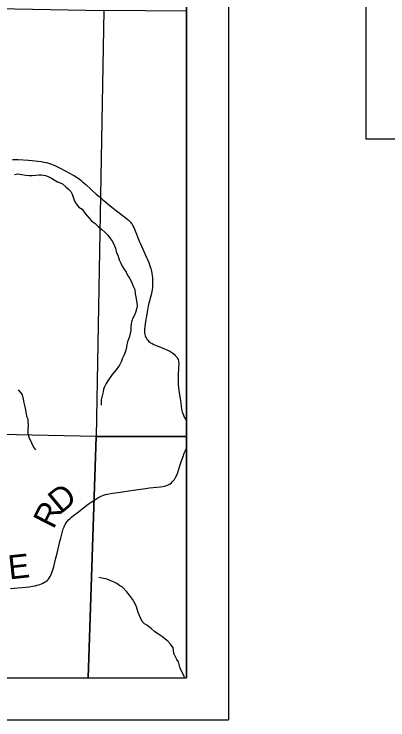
# Model space of a CAD drawing. Extents: x -7.1 to 34, y 0 to 22.
# Drawn here: x 8.492 to 9.377, y 14 to 15.673 of the extents above; entities that cross this region are included whole.
import ezdxf

# ---------------------------------------------------------------- set-up
doc = ezdxf.new("R2010")
doc.units = 0
for name, color, linetype in [('GM_X_County_Road', 7, 'Continuous'), ('GM_X_County_Road_Text', 7, 'Continuous'), ('GM_X_Minor_River', 7, 'Continuous'), ('GM_X_Section', 7, 'Continuous'), ('GM_X_Township_Road', 7, 'Continuous'), ('GM_X_Unincorporated', 7, 'Continuous'), ('SH_Cut_Line', 7, 'Continuous'), ('SH_Data', 7, 'Continuous'), ('SH_Text', 7, 'Continuous')]:
    doc.layers.add(name, color=color, linetype=linetype)

msp = doc.modelspace()

# ---------------------------------------------------------------- linework, layer by layer
at = {"layer": 'GM_X_County_Road'}
for points in [[(8.4874, 15.3285), (8.5008, 15.3278), (8.5254, 15.3267), (8.5342, 15.3258), (8.5479, 15.3241), (8.5556, 15.3231), (8.5623, 15.322), (8.5681, 15.3207), (8.5734, 15.3191), (8.5799, 15.317), (8.5844, 15.3154), (8.5929, 15.3119), (8.601, 15.3079), (8.6247, 15.2951), (8.6303, 15.292), (8.6348, 15.2891), (8.6406, 15.2855), (8.6463, 15.2815), (8.6503, 15.2786), (8.6539, 15.2755), (8.6614, 15.2686), (8.6731, 15.2579), (8.6774, 15.2539), (8.6863, 15.2461), (8.6933, 15.2401), (8.7008, 15.2337), (8.7088, 15.2271), (8.7193, 15.2183), (8.7375, 15.2037), (8.7609, 15.1856), (8.7641, 15.183), (8.7667, 15.1804), (8.7692, 15.1774), (8.771, 15.1747), (8.7732, 15.1711), (8.7751, 15.1671), (8.7771, 15.1628), (8.7887, 15.1331), (8.7908, 15.1279), (8.7971, 15.1142), (8.802, 15.1033), (8.8105, 15.0841), (8.8126, 15.0788), (8.8143, 15.0734), (8.8155, 15.0694), (8.817, 15.0631), (8.8181, 15.058), (8.8187, 15.0535), (8.8192, 15.0475), (8.8194, 15.0408), (8.8195, 15.0388)], [(8.8195, 15.0388), (8.8196, 15.0348), (8.8197, 15.0293), (8.8196, 15.0246), (8.819, 15.0194), (8.8183, 15.0155), (8.816, 15.0072), (8.8107, 14.9879), (8.8089, 14.9806), (8.8073, 14.9714), (8.8054, 14.9576), (8.8039, 14.948), (8.8024, 14.9395), (8.8011, 14.9308), (8.8008, 14.9274), (8.8006, 14.9233), (8.8007, 14.9198), (8.8009, 14.9162), (8.8014, 14.9133), (8.8021, 14.9102), (8.8029, 14.9081), (8.8042, 14.9055), (8.8063, 14.9022), (8.8084, 14.8996), (8.8099, 14.8979), (8.8129, 14.8953), (8.8149, 14.8939), (8.8186, 14.8918), (8.823, 14.8896), (8.8268, 14.8878), (8.8397, 14.8826), (8.8462, 14.8801), (8.8531, 14.8772), (8.8589, 14.8743), (8.8629, 14.8719), (8.8653, 14.8705), (8.8676, 14.8689), (8.8708, 14.8664), (8.8734, 14.8639), (8.8761, 14.8608), (8.8776, 14.8585), (8.8789, 14.8565), (8.88, 14.8541), (8.8809, 14.8513), (8.8815, 14.8483), (8.8817, 14.845), (8.8816, 14.8415), (8.8815, 14.8367), (8.8811, 14.8291), (8.8807, 14.8225), (8.8802, 14.8111), (8.88, 14.8029), (8.8805, 14.7951), (8.8811, 14.7885), (8.8821, 14.7807), (8.8835, 14.7706), (8.8857, 14.7568), (8.8875, 14.744), (8.8886, 14.7366), (8.89, 14.7304), (8.8915, 14.7258), (8.8929, 14.7218), (8.8948, 14.7177), (8.899, 14.7101), (8.9, 14.7083)], [(8.4833, 14.3112), (8.5184, 14.3145), (8.527, 14.3154), (8.5356, 14.3167), (8.5418, 14.3179), (8.5464, 14.319), (8.5523, 14.3208), (8.5564, 14.3222), (8.5596, 14.3237), (8.5637, 14.3261), (8.5665, 14.3278), (8.5697, 14.3304), (8.572, 14.3328), (8.5745, 14.3358), (8.5768, 14.3397), (8.5786, 14.343), (8.5803, 14.3466), (8.5821, 14.3511), (8.5835, 14.3558), (8.5853, 14.3624), (8.5889, 14.378), (8.5932, 14.3949), (8.5975, 14.4123), (8.6, 14.4228), (8.6019, 14.4308), (8.6059, 14.4462), (8.6079, 14.4525), (8.6098, 14.4573), (8.6112, 14.4602), (8.6125, 14.4628), (8.6148, 14.4667), (8.6172, 14.47), (8.6205, 14.4738), (8.6233, 14.4766), (8.6272, 14.4803), (8.6326, 14.4847), (8.6411, 14.4911), (8.6559, 14.5023), (8.6673, 14.5109), (8.6741, 14.5157), (8.6853, 14.5233), (8.6901, 14.5262), (8.6949, 14.5287), (8.6994, 14.5309), (8.7034, 14.5326), (8.7084, 14.5341), (8.7125, 14.5353), (8.7196, 14.5364), (8.7487, 14.5408), (8.7679, 14.5437), (8.8026, 14.5486), (8.8127, 14.5497), (8.8213, 14.5507), (8.8384, 14.5523), (8.8443, 14.5531), (8.8483, 14.5541), (8.8524, 14.5554), (8.8564, 14.5571), (8.859, 14.5584), (8.8612, 14.5598), (8.8645, 14.5622), (8.8671, 14.5646), (8.8693, 14.567), (8.8715, 14.5697), (8.8735, 14.5729), (8.8752, 14.5757), (8.8782, 14.5818), (8.8796, 14.586), (8.8842, 14.6018), (8.8866, 14.6089), (8.8888, 14.6163), (8.8918, 14.6244), (8.8948, 14.6318), (8.8978, 14.6383), (8.9, 14.6426)]]:
    msp.add_lwpolyline(points, dxfattribs=at)
at = {"layer": 'GM_X_Minor_River'}
for points in [[(8.4925, 15.2922), (8.5, 15.2945), (8.5098, 15.2922), (8.5182, 15.2907), (8.5273, 15.2899), (8.5345, 15.2899), (8.5428, 15.291), (8.55, 15.2921), (8.5561, 15.2921), (8.5656, 15.2905), (8.572, 15.2882), (8.58, 15.284), (8.5864, 15.2798), (8.5947, 15.2752), (8.6004, 15.2729), (8.6061, 15.2702), (8.614, 15.263), (8.6201, 15.258), (8.6258, 15.2523), (8.6291, 15.2458), (8.6321, 15.2367), (8.6348, 15.2295), (8.6389, 15.2234), (8.645, 15.2154), (8.6525, 15.2104), (8.6578, 15.2032), (8.6638, 15.1952), (8.6752, 15.183), (8.6835, 15.1761), (8.6918, 15.1688), (8.6994, 15.1623), (8.7069, 15.1562), (8.7133, 15.1486), (8.7198, 15.1402), (8.7247, 15.1338), (8.7296, 15.1235), (8.7318, 15.1178), (8.7344, 15.1071), (8.7374, 15.1014), (8.7404, 15.0904), (8.7442, 15.0824), (8.7476, 15.0755), (8.7517, 15.0691), (8.7574, 15.0611), (8.7611, 15.0527), (8.7656, 15.0462), (8.7717, 15.034), (8.7739, 15.0276), (8.7773, 15.0203), (8.7788, 15.0101), (8.7803, 15.0025), (8.7825, 14.988), (8.7832, 14.9812), (8.7824, 14.9755), (8.7793, 14.9656), (8.7767, 14.9592), (8.7732, 14.9519), (8.7709, 14.9459), (8.769, 14.9398), (8.7678, 14.9307), (8.7678, 14.9235), (8.7666, 14.9155), (8.7651, 14.9083), (8.7628, 14.9022), (8.7604, 14.8957), (8.7585, 14.8897), (8.7577, 14.8836), (8.7566, 14.8764), (8.7543, 14.8692), (8.7516, 14.8635), (8.7478, 14.8559), (8.7462, 14.8502), (8.7416, 14.8403), (8.7336, 14.8297), (8.7237, 14.8184), (8.7149, 14.8062), (8.7099, 14.7971), (8.7061, 14.7892), (8.7034, 14.7835), (8.7023, 14.7774), (8.7007, 14.7709), (8.6996, 14.7652), (8.698, 14.7584), (8.6976, 14.7523), (8.6976, 14.7459)], [(8.5008, 14.7819), (8.5068, 14.7762), (8.5106, 14.7705), (8.5129, 14.7602), (8.5147, 14.7515), (8.5166, 14.7416), (8.5184, 14.7351), (8.521, 14.7199), (8.5237, 14.7134), (8.5244, 14.7062), (8.5247, 14.6978), (8.5239, 14.6891), (8.5243, 14.6796), (8.5265, 14.6693), (8.5303, 14.6625), (8.5329, 14.6568), (8.5378, 14.6465), (8.5419, 14.64)], [(8.8952, 14.1), (8.8944, 14.1026), (8.8906, 14.1117), (8.8869, 14.1189), (8.8846, 14.1247), (8.8809, 14.1376), (8.8775, 14.1433), (8.8741, 14.1494), (8.8704, 14.1574), (8.8692, 14.165), (8.8681, 14.1707), (8.8621, 14.1791), (8.8557, 14.1867), (8.8493, 14.1913), (8.8432, 14.1966), (8.8364, 14.2016), (8.8254, 14.2085), (8.816, 14.2169), (8.8061, 14.2245), (8.8005, 14.2276), (8.7952, 14.2333), (8.7907, 14.2416), (8.7876, 14.2489), (8.7854, 14.2546), (8.7839, 14.2603), (8.7809, 14.2702), (8.7753, 14.2805), (8.7719, 14.2862), (8.7677, 14.2927), (8.7587, 14.3037), (8.7481, 14.3144), (8.7424, 14.3174), (8.7352, 14.3235), (8.7288, 14.3262), (8.7208, 14.3297), (8.7117, 14.3335), (8.7042, 14.3347), (8.6958, 14.337), (8.6925, 14.3374)]]:
    msp.add_lwpolyline(points, dxfattribs=at)
at = {"layer": 'GM_X_Section'}
msp.add_lwpolyline([(7.6901, 15.7003), (8.7045, 15.6816), (8.6861, 14.6719), (7.6641, 14.6933)], close=True, dxfattribs=at)
at = {"layer": 'GM_X_Township_Road'}
msp.add_lwpolyline([(6.633, 14.1), (8.9, 14.1), (8.9, 17.7079), (8.6668, 17.7136), (8.4472, 17.7189), (7.7202, 17.7285), (6.7118, 17.7486), (6.7058, 17.2839), (6.6822, 16.3488), (6.6748, 15.9993), (6.6586, 15.2372), (6.6565, 15.1357)], close=True, dxfattribs=at)
at = {"layer": 'GM_X_Unincorporated'}
for points in [[(8.9, 14.6715), (8.9, 15.6794), (8.7045, 15.6816), (8.6861, 14.6719)], [(7.6503, 14.1), (8.6671, 14.1), (8.6861, 14.6719), (7.6641, 14.6933)], [(8.6671, 14.1), (8.9, 14.1), (8.9, 14.6715), (8.6861, 14.6719)]]:
    msp.add_lwpolyline(points, close=True, dxfattribs=at)
at = {"layer": 'SH_Cut_Line'}
msp.add_lwpolyline([(2.1, 17.7253), (2.1, 14.1), (8.9, 14.1), (8.9, 17.7079), (8.6668, 17.7136), (8.4472, 17.7189), (7.7202, 17.7285), (6.7118, 17.7486), (6.3575, 17.7557), (6.1904, 17.7592), (5.7514, 17.7685), (5.5047, 17.7737), (5.1115, 17.7819), (5.0544, 17.7831), (5.0443, 17.7832), (4.7094, 17.7848), (4.5657, 17.7857), (4.3, 17.7873), (3.8304, 17.7952), (3.8238, 17.6717), (3.7215, 17.6707), (3.0659, 17.6986), (2.7886, 17.7105), (2.5551, 17.7155)], close=True, dxfattribs=at)
at = {"layer": 'SH_Data'}
for p, q in [((9, 21), (9, 14)), ((8.9, 20.9), (8.9, 14.1)), ((2.1, 14.1), (8.9, 14.1)), ((2, 14), (9, 14))]:
    msp.add_line(p, q, dxfattribs=at)
at = {"layer": 'SH_Text'}
msp.add_lwpolyline([(9.3262, 15.8766), (10.9505, 15.8766), (10.9505, 15.3766), (9.3262, 15.3766)], close=True, dxfattribs=at)

# ---------------------------------------------------------------- texts
at = {"layer": 'GM_X_County_Road_Text'}
for s, rotation, p in [('D', 39.6008, (8.602, 14.4869)), ('R', 63.1435, (8.5848, 14.45)), ('E', 6.1537, (8.4803, 14.3328))]:
    msp.add_text(s, height=0.0568, rotation=rotation, dxfattribs=at).set_placement(p)

doc.saveas('drawing.dxf')
